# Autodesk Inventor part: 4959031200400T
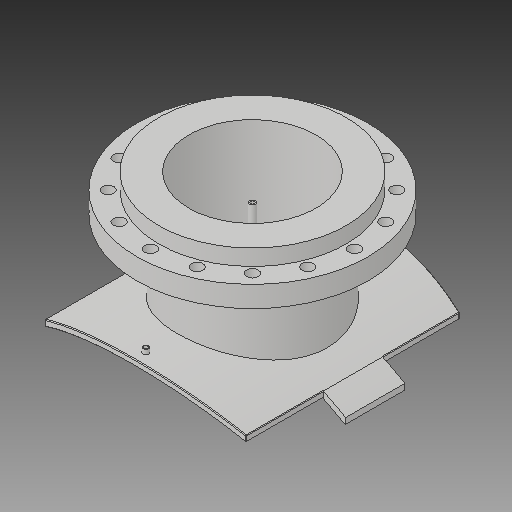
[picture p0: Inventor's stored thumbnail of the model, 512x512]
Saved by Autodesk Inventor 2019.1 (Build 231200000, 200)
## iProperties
Created: 2017-10
Part Number: 4959031200400T
Material: Generic
Description: PLASSON FLANGED BRANCH SADDLE 1200X400
Document SubType Name: Modeling
Designer: KIM
Mass: 2339.99 g
Surface Area: 3251.55 cm^2
Volume: 2339.99 cm^3
Density: 1 g/cm^3
Appearance: Default
Author: KIM
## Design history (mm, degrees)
derived "495904_495903.ipt"
feature "Solid1::495904_495903.ipt"
feature "Solid2::495904_495903.ipt"
tag "TaggingFeature1"
body "Solid1"
other parameters: "d1" = 15, "d2" = 516.6, "d4" = 0, "d6" = 152.5, "d7" = 0, "d12" = 625.6, "d13" = 14, "d14" = 274.5, "d16" = 5 deg, "d18" = 4, "d19" = 14, "d20" = 0, "d21" = 3, "d22" = 0, "d23" = 895, "d36" = 274.5, "d38" = 0, "d39" = 2, "d41" = 327, "d42" = 482, "d43" = 595, "d44" = 224, "d46" = 385.6, "d47" = 16, "d48" = 10.4, "d49" = 196, "d51" = 1224, "d53" = 0, "d55" = 262.5, "d57" = 0, "d59" = 360 deg, "d61" = 54, "d63" = 0, "d67" = 15, "d70" = 0, "d71" = 2, "d72" = 574, "d_1" = 482, "B_" = 574, "x_" = 15, "D_" = 16, "DN_" = 327, "D_1" = 595, "t_" = 54, "Dp_" = 525
